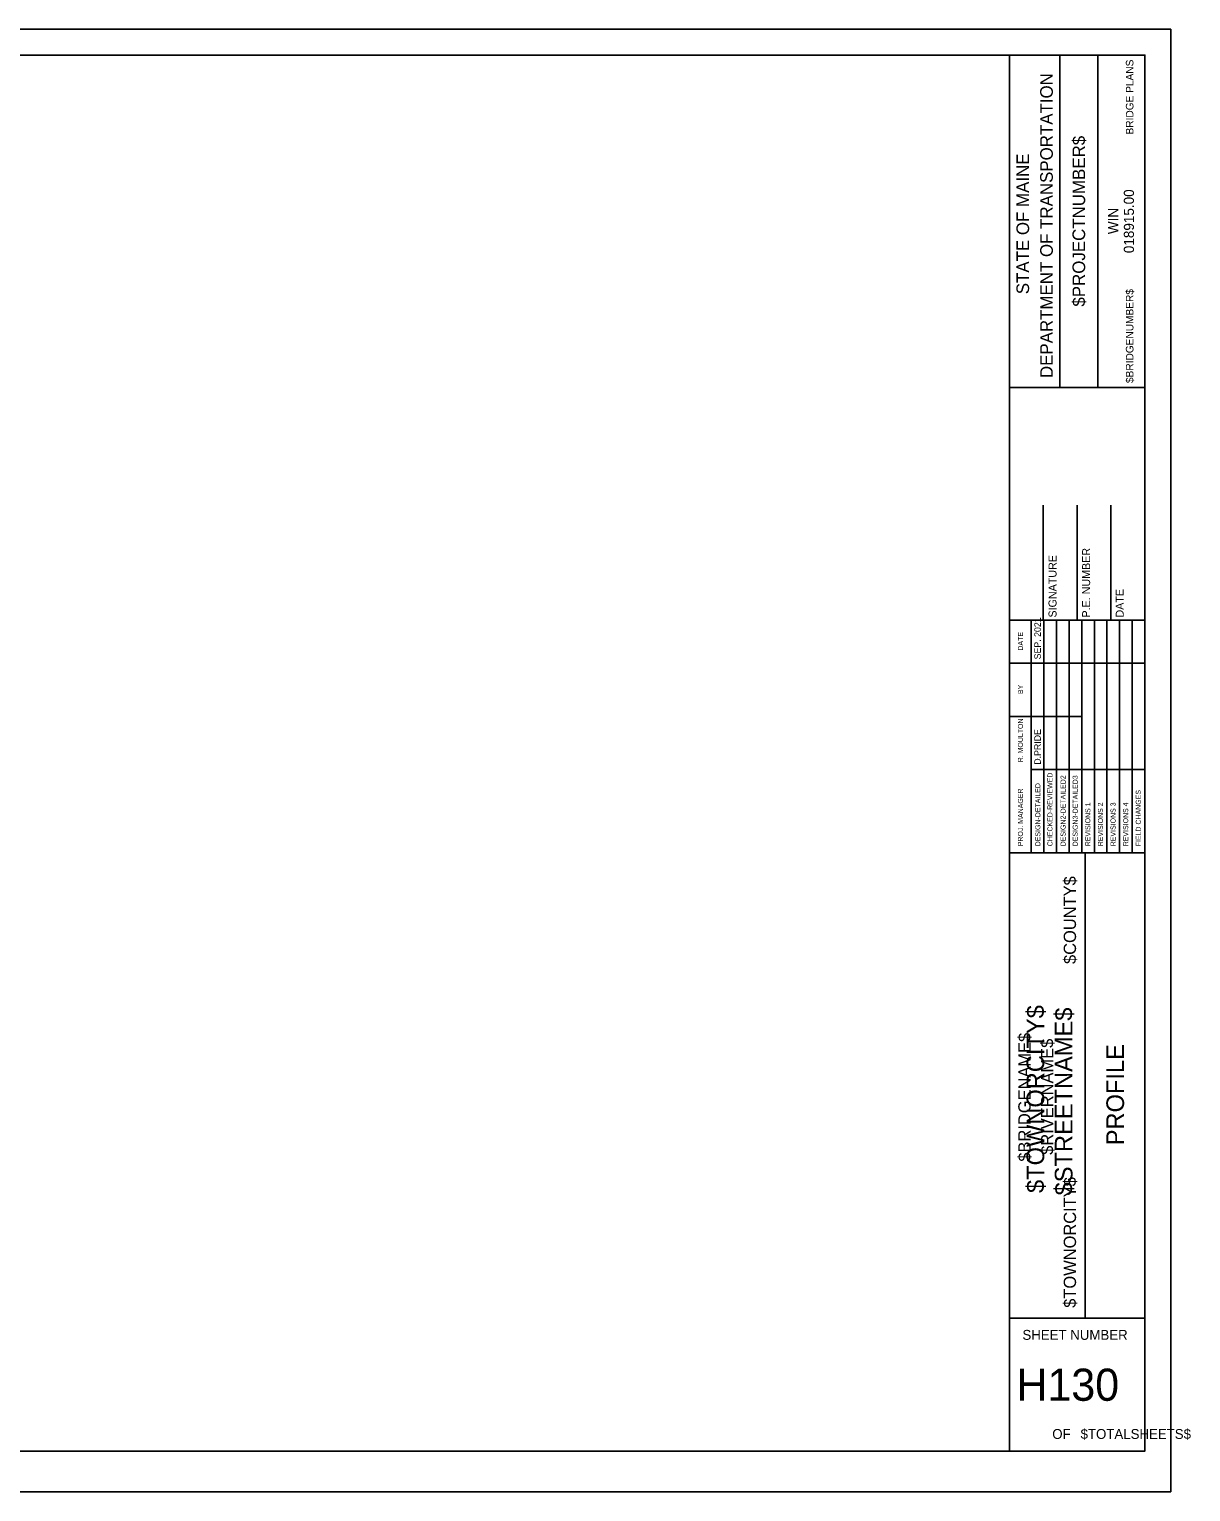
# Model space of a CAD drawing. Extents: x 173722 to 174580, y 9985 to 10525.
# Drawn here: x 174151 to 174580, y 9985 to 10525 of the extents above; entities that cross this region are included whole.
import ezdxf

# ---------------------------------------------------------------- set-up
doc = ezdxf.new("R2010")
doc.units = 0
for name, color, linetype in [('BORDER', 7, 'Continuous'), ('BRIDGE_TITLE', 7, 'Continuous'), ('CLIPS', 7, 'Continuous'), ('HIGHWAY_TITLE', 7, 'Continuous'), ('PLOT BOUNDARY', 7, 'Continuous')]:
    doc.layers.add(name, color=color, linetype=linetype)

msp = doc.modelspace()

# ---------------------------------------------------------------- linework, layer by layer
at = {"layer": 'BORDER'}
for p, q in [((174512.93, 10000), (174512.93, 10515)), ((174531.57, 10392.37), (174531.57, 10514.99)), ((174545.54, 10392.37), (174545.54, 10514.99)), ((174512.93, 10392.35), (174562.93, 10392.35)), ((174525.43, 10306.56), (174525.43, 10348.98)), ((174537.93, 10306.56), (174537.93, 10348.98)), ((174550.43, 10306.56), (174550.43, 10348.98)), ((174512.93, 10306.56), (174562.93, 10306.56)), ((174512.93, 10220.73), (174562.93, 10220.73)), ((174540.88, 10049.06), (174540.88, 10220.73)), ((174512.93, 10049.06), (174562.93, 10049.06))]:
    msp.add_line(p, q, dxfattribs=at)
msp.add_lwpolyline([(173762.93, 10515), (174562.93, 10515), (174562.93, 10000), (173762.93, 10000)], close=True, dxfattribs=at)
for points in [[(174521, 10290.62), (174521, 10306.56)], [(174525.66, 10220.74), (174525.66, 10306.56)], [(174530.32, 10306.56), (174530.32, 10220.74)], [(174534.98, 10220.74), (174534.98, 10306.56)], [(174539.64, 10220.74), (174539.64, 10306.56)], [(174544.3, 10220.74), (174544.3, 10306.56)], [(174548.96, 10220.74), (174548.96, 10306.56)], [(174553.61, 10220.74), (174553.61, 10306.56)], [(174558.27, 10220.74), (174558.27, 10306.56)], [(174521.01, 10220.74), (174521.01, 10303.1)], [(174512.93, 10290.62), (174562.93, 10290.62)], [(174512.93, 10271), (174521.01, 10271)], [(174521, 10271), (174539.63, 10271)], [(174521, 10251.38), (174562.93, 10251.38)]]:
    msp.add_lwpolyline(points, dxfattribs=at)
at = {"layer": 'CLIPS'}
msp.add_lwpolyline([(173762.93, 10000), (174512.93, 10000), (174512.93, 10515), (173762.93, 10515)], close=True, dxfattribs=at)
at = {"layer": 'PLOT BOUNDARY'}
msp.add_lwpolyline([(173722.46, 9985), (174572.46, 9985), (174572.46, 10524.52), (173722.46, 10524.52)], close=True, dxfattribs=at)

# ---------------------------------------------------------------- texts
at = {"layer": 'BORDER'}
for s, height, rotation, p in [('DEPARTMENT OF TRANSPORTATION', 4.6588, 90, (174528.96, 10395.84)), ('$PROJECTNUMBER$', 4.6588, 90, (174540.89, 10422.2)), ('STATE OF MAINE', 4.6588, 90, (174520.2, 10426.77)), ('018915.00', 3.726, 90, (174558.9, 10441.91)), ('WIN', 3.726, 90, (174553.11, 10448.93)), ('P.E. NUMBER', 2.9528, 90, (174542.73, 10307.5)), ('SIGNATURE', 2.953, 90, (174530.33, 10307.5)), ('DATE', 2.953, 90, (174555.13, 10307.5)), ('SEP. 2021', 2.423, 90, (174524.54, 10292.07)), ('DATE', 1.857, 90, (174517.95, 10295.31)), ('BY', 1.857, 90, (174517.95, 10279.27)), ('R. MOULTON', 1.864, 90, (174517.95, 10254.09)), ('D.PRIDE', 2.423, 90, (174524.54, 10253.21)), ('DESIGN-DETAILED', 1.8637, 90, (174524.36, 10223.12)), ('CHECKED-REVIEWED', 1.8637, 90, (174528.83, 10223.12)), ('DESIGN2-DETAILED2', 1.8637, 90, (174533.68, 10223.12)), ('DESIGN3-DETAILED3', 1.8637, 90, (174538.15, 10223.12)), ('PROJ. MANAGER', 1.8637, 90, (174517.95, 10223.12)), ('FIELD CHANGES', 1.8637, 90, (174561.44, 10223.12)), ('REVISIONS 1', 1.8637, 90, (174542.81, 10223.12)), ('REVISIONS 2', 1.8637, 90, (174547.47, 10223.12)), ('REVISIONS 3', 1.8637, 90, (174552.12, 10223.12)), ('REVISIONS 4', 1.8637, 90, (174556.78, 10223.12)), ('PROFILE', 6.521, 90, (174555.25, 10112.81)), ('SHEET NUMBER', 3.6554, 360, (174517.75, 10041.04)), ('OF', 3.655, 360, (174528.76, 10004.48)), ('$TOTALSHEETS$', 3.6554, 360, (174539.21, 10004.48))]:
    msp.add_text(s, height=height, rotation=rotation, dxfattribs=at).set_placement(p)
msp.add_text('H130', height=11.867, dxfattribs=at).set_placement((174515.5, 10018.55))
at = {"layer": 'BRIDGE_TITLE'}
for s, height, p in [('BRIDGE PLANS', 2.795, (174558.72, 10485.69)), ('$BRIDGENUMBER$', 2.795, (174558.72, 10394)), ('$COUNTY$', 4.536, (174537.53, 10179.69)), ('$BRIDGENAME$', 4.5358, (174520.76, 10106.78)), ('$RIVERNAME$', 4.5358, (174529.14, 10109.31)), ('$TOWNORCITY$', 4.5358, (174537.53, 10052.86))]:
    msp.add_text(s, height=height, rotation=90, dxfattribs=at).set_placement(p)
at = {"layer": 'HIGHWAY_TITLE'}
for s, p in [('$TOWNORCITY$', (174525.79, 10095.21)), ('$STREETNAME$', (174536.22, 10094.32))]:
    msp.add_text(s, height=6.5214, rotation=90, dxfattribs=at).set_placement(p)

doc.saveas('drawing.dxf')
